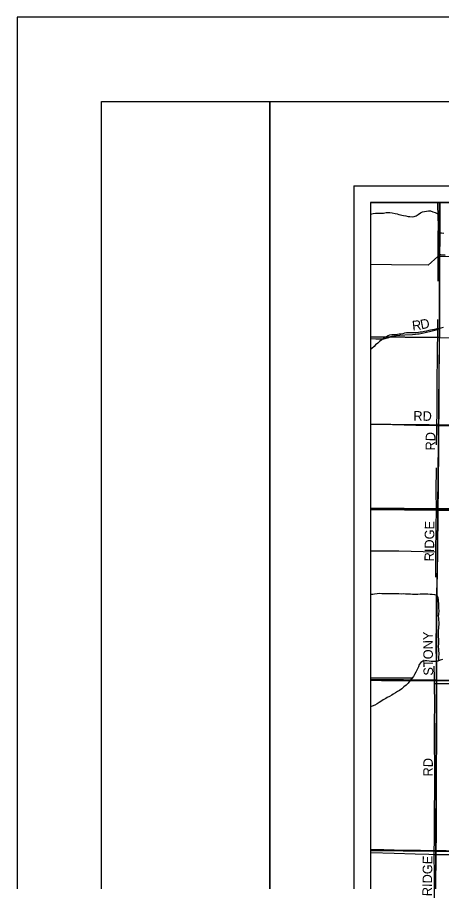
# Model space of a CAD drawing. Extents: x 0 to 34, y 0 to 22.
# Drawn here: x 0 to 2.52, y 16.87 to 22 of the extents above; entities that cross this region are included whole.
import ezdxf

# ---------------------------------------------------------------- set-up
doc = ezdxf.new("R2010")
doc.units = 0
for name, color, linetype in [('GM_X_City_Street', 7, 'Continuous'), ('GM_X_County_Road', 7, 'Continuous'), ('GM_X_County_Road_Text', 7, 'Continuous'), ('GM_X_Major_River', 7, 'Continuous'), ('GM_X_Minor_River', 7, 'Continuous'), ('GM_X_Section', 7, 'Continuous'), ('GM_X_State_Route', 7, 'Continuous'), ('GM_X_Township_Road', 7, 'Continuous'), ('GM_X_Township_Road_Text', 7, 'Continuous'), ('GM_X_US_Route', 7, 'Continuous'), ('SH_Border', 7, 'Continuous'), ('SH_Cut_Line', 7, 'Continuous'), ('SH_Data', 7, 'Continuous')]:
    doc.layers.add(name, color=color, linetype=linetype)

msp = doc.modelspace()

# ---------------------------------------------------------------- linework, layer by layer
at = {"layer": 'GM_X_City_Street'}
for points in [[(2.5083, 20.9), (2.1, 20.9), (2.1, 20.1033), (2.509, 20.0994)], [(3.5146, 20.9), (2.5083, 20.9), (2.509, 20.0994), (3.5083, 20.0811)], [(2.1, 20.1033), (2.1, 19.086), (2.4993, 19.0815), (2.509, 20.0994)], [(2.1, 19.086), (2.1, 18.0672), (2.4915, 18.0628), (2.4993, 19.0815)], [(2.1, 18.0672), (2.1, 17.0529), (2.4879, 17.0483), (2.4915, 18.0628)], [(2.1, 17.0529), (2.1, 16.0468), (2.4708, 16.042), (2.4803, 16.0422), (2.4865, 16.4094), (2.4879, 17.0483)]]:
    msp.add_lwpolyline(points, close=True, dxfattribs=at)
at = {"layer": 'GM_X_County_Road'}
for points in [[(2.5122, 20.5909), (2.5122, 20.5937), (2.5121, 20.6161), (2.5125, 20.6596), (2.5124, 20.7062), (2.5126, 20.7603), (2.5128, 20.7796), (2.513, 20.8363), (2.5134, 20.8803), (2.5135, 20.9)], [(2.5097, 20.1502), (2.5097, 20.1609), (2.5102, 20.1988), (2.5108, 20.3033), (2.511, 20.3791), (2.5113, 20.4463), (2.5121, 20.5234), (2.5121, 20.5533), (2.5121, 20.575), (2.5122, 20.5909)], [(2.5062, 19.5803), (2.5069, 19.6454), (2.507, 19.6853), (2.5071, 19.712), (2.5076, 19.7735), (2.5077, 19.8165), (2.5079, 19.8401), (2.5082, 19.8861), (2.5082, 19.906), (2.5087, 19.975), (2.509, 20.0304), (2.5092, 20.0763), (2.5094, 20.1111), (2.5096, 20.1435), (2.5097, 20.1502)], [(2.5016, 19.0733), (2.502, 19.114), (2.503, 19.1644), (2.5032, 19.2048), (2.5033, 19.226), (2.5038, 19.2944), (2.5047, 19.3677), (2.5052, 19.4119), (2.5053, 19.4492), (2.5062, 19.5338), (2.5062, 19.5742), (2.5062, 19.5803)], [(2.4932, 18.0623), (2.4936, 18.0677), (2.4937, 18.0694), (2.4938, 18.0714), (2.4938, 18.0995), (2.4938, 18.1225), (2.4935, 18.1399), (2.4925, 18.1667), (2.491, 18.2046), (2.4902, 18.2362), (2.4904, 18.3245), (2.4906, 18.36), (2.4908, 18.4128), (2.491, 18.4968), (2.4912, 18.5372), (2.4915, 18.5521), (2.4932, 18.5912), (2.495, 18.6378), (2.4972, 18.6844), (2.4979, 18.7024), (2.4982, 18.7279), (2.4987, 18.8025), (2.4992, 18.8585), (2.4995, 18.9058), (2.5004, 18.9909), (2.5013, 19.0456), (2.5016, 19.0699), (2.5016, 19.0723), (2.5016, 19.0733)]]:
    msp.add_lwpolyline(points, dxfattribs=at)
at = {"layer": 'GM_X_Major_River'}
msp.add_lwpolyline([(2.5271, 18.1874), (2.5133, 18.182), (2.4995, 18.1769), (2.4866, 18.1745), (2.4733, 18.174), (2.46, 18.1746), (2.4475, 18.1764), (2.4335, 18.1786), (2.4237, 18.1788), (2.4103, 18.1764), (2.3977, 18.1694), (2.3883, 18.1559), (2.3835, 18.1434), (2.3784, 18.131), (2.3681, 18.1107), (2.3614, 18.0971), (2.354, 18.0847), (2.3431, 18.0712), (2.333, 18.0589), (2.3229, 18.0469), (2.3113, 18.035), (2.2978, 18.0242), (2.2855, 18.0127), (2.2716, 18.003), (2.259, 17.9964), (2.2471, 17.9891), (2.234, 17.9806), (2.225, 17.9745), (2.2123, 17.9676), (2.1992, 17.9602), (2.1894, 17.9557), (2.1754, 17.9471), (2.1611, 17.9379), (2.1511, 17.9309), (2.1384, 17.9235), (2.1243, 17.9162), (2.1093, 17.9092), (2.1, 17.9052)], dxfattribs=at)
at = {"layer": 'GM_X_Minor_River'}
msp.add_line((2.3466, 18.0756), (2.1, 18.0766), dxfattribs=at)
for points in [[(2.4969, 20.9), (2.4971, 20.8695), (2.4985, 20.8391), (2.4999, 20.8329), (2.5008, 20.747), (2.5001, 20.7208), (2.4996, 20.6235), (2.4987, 20.5797), (2.5001, 20.4938), (2.5002, 20.4326)], [(2.1, 20.8316), (2.1146, 20.8352), (2.128, 20.8371), (2.1375, 20.8376), (2.1595, 20.837), (2.1762, 20.8377), (2.1926, 20.8399), (2.2044, 20.841), (2.2146, 20.8411), (2.2278, 20.8388), (2.2452, 20.8349), (2.2576, 20.8323), (2.2674, 20.8297), (2.2946, 20.8229), (2.3089, 20.8202), (2.3222, 20.8179), (2.332, 20.8168), (2.3464, 20.8153), (2.3582, 20.8165), (2.3704, 20.8203), (2.3828, 20.8287), (2.3972, 20.8389), (2.4076, 20.844), (2.4194, 20.847), (2.4316, 20.8493), (2.4438, 20.8509), (2.4563, 20.8498), (2.4691, 20.8456), (2.483, 20.8414), (2.4999, 20.8329)], [(2.5001, 20.7208), (2.5221, 20.7194), (2.5342, 20.7187)], [(3.1282, 20.5752), (3.0655, 20.5771), (2.9928, 20.5751), (2.9386, 20.5755), (2.8853, 20.5713), (2.8318, 20.5713), (2.7919, 20.571), (2.7441, 20.5719), (2.6865, 20.5751), (2.6114, 20.5765), (2.5431, 20.5796), (2.4987, 20.5797), (2.4415, 20.5289), (2.224, 20.5306), (2.1, 20.5313)], [(2.4975, 20.2053), (2.4967, 20.1486), (2.4955, 20), (2.4943, 19.8248), (2.4925, 19.6552), (2.4909, 19.5747), (2.4904, 19.4606)], [(2.5304, 20.1583), (2.5166, 20.1549), (2.5059, 20.1526), (2.4925, 20.1491), (2.4799, 20.1465), (2.4669, 20.1438), (2.4555, 20.1422), (2.4452, 20.1402), (2.4318, 20.1364), (2.4192, 20.1334), (2.4051, 20.1311), (2.3944, 20.1295), (2.3837, 20.1283), (2.37, 20.1272), (2.3602, 20.1267), (2.3469, 20.1263), (2.3343, 20.1267), (2.3222, 20.1263), (2.3127, 20.1254), (2.302, 20.1234), (2.2905, 20.1211), (2.2798, 20.1191), (2.2692, 20.1175), (2.2596, 20.1159), (2.2471, 20.1147), (2.2368, 20.1143), (2.2254, 20.1138), (2.2121, 20.1116), (2.2017, 20.1077), (2.1886, 20.1005), (2.1762, 20.0917), (2.1657, 20.0844), (2.1529, 20.0749), (2.1428, 20.0653), (2.1299, 20.0542), (2.1202, 20.0454), (2.1081, 20.0339), (2.1, 20.0265)], [(3.1233, 19.571), (2.8675, 19.5726), (2.6853, 19.5733), (2.4909, 19.5747), (2.3688, 19.5767), (2.1601, 19.5815), (2.1, 19.5823)], [(2.4887, 19.3238), (2.4882, 19.1847), (2.4886, 19.0805), (2.4869, 18.9668), (2.4863, 18.8247), (2.4851, 18.6753)], [(2.7507, 19.0855), (2.7454, 19.0819), (2.7403, 19.0816), (2.557, 19.0812), (2.4886, 19.0805), (2.3679, 19.0801), (2.2856, 19.0817), (2.2529, 19.0812)], [(2.4863, 18.8247), (2.2677, 18.829), (2.1, 18.8298)], [(2.5047, 18.1788), (2.5051, 18.1941), (2.5062, 18.2044), (2.5069, 18.2165), (2.5068, 18.2268), (2.5056, 18.2363), (2.5044, 18.2489), (2.504, 18.2607), (2.5046, 18.2812), (2.5054, 18.2964), (2.505, 18.3089), (2.5037, 18.3185), (2.5025, 18.3284), (2.5024, 18.3379), (2.5027, 18.3493), (2.5034, 18.3599), (2.5044, 18.3698), (2.5048, 18.3812), (2.5063, 18.3948), (2.5063, 18.4074), (2.5051, 18.4203), (2.5047, 18.4318), (2.5043, 18.4439), (2.5057, 18.4545), (2.5064, 18.477), (2.506, 18.4899), (2.5055, 18.4998), (2.5046, 18.5093), (2.5046, 18.5211), (2.5041, 18.5314), (2.5033, 18.5413), (2.5006, 18.5543), (2.4945, 18.567), (2.4821, 18.5708), (2.4662, 18.5728), (2.4544, 18.5727), (2.4408, 18.5743), (2.4268, 18.575), (2.4169, 18.5746), (2.407, 18.5737), (2.3937, 18.5737), (2.3796, 18.5718), (2.3633, 18.5715), (2.3496, 18.5723), (2.3379, 18.5742), (2.3209, 18.575), (2.3072, 18.5751), (2.2939, 18.5758), (2.2833, 18.5754), (2.2678, 18.5762), (2.2571, 18.5765), (2.2446, 18.5761), (2.2298, 18.5758), (2.2192, 18.5757), (2.2089, 18.5756), (2.196, 18.5756), (2.1835, 18.5756), (2.1672, 18.5772), (2.1535, 18.5776), (2.1391, 18.5768), (2.1238, 18.5746), (2.1132, 18.5734), (2.1018, 18.5722), (2.1, 18.5728)], [(2.476, 18.1459), (2.4771, 18.0771), (2.4781, 18.0432), (2.4793, 17.9146), (2.4784, 17.8158), (2.4785, 17.6976), (2.4786, 17.5432), (2.4789, 17.4216), (2.4779, 17.2775), (2.4774, 17.1296), (2.4761, 17.0289), (2.4773, 16.9103), (2.4771, 16.7989), (2.4777, 16.6578), (2.479, 16.5464), (2.4756, 16.3998), (2.474, 16.2629), (2.4723, 16.1379), (2.4714, 16.025)], [(2.4788, 18.0443), (2.6292, 18.0442), (2.7981, 18.0431), (2.9662, 18.0429), (2.9984, 18.0416), (3.1078, 18.0415)], [(2.1, 17.04), (2.1033, 17.04), (2.2406, 17.0361), (2.3642, 17.0318), (2.4454, 17.0298), (2.4761, 17.0289), (2.5638, 17.0291), (2.6591, 17.029), (2.7445, 17.0292), (2.8488, 17.0277), (2.8978, 17.0267)]]:
    msp.add_lwpolyline(points, dxfattribs=at)
at = {"layer": 'GM_X_Section'}
for points in [[(2.509, 20.0994), (3.5083, 20.0811), (3.5044, 19.0749), (2.4993, 19.0815)], [(3.5044, 19.0749), (3.5019, 18.057), (2.4915, 18.0628), (2.4993, 19.0815)], [(3.5019, 18.057), (3.4934, 17.0475), (2.4879, 17.0483), (2.4915, 18.0628)]]:
    msp.add_lwpolyline(points, close=True, dxfattribs=at)
msp.add_lwpolyline([(3.4773, 16.1435), (3.4754, 16.0365), (3.4686, 16.0366), (2.4803, 16.0422), (2.4865, 16.4094), (2.4879, 17.0483), (3.4934, 17.0475), (3.4907, 16.8935)], dxfattribs=at)
at = {"layer": 'GM_X_State_Route'}
msp.add_lwpolyline([(2.1, 18.0629), (2.1654, 18.0625), (2.198, 18.0623), (2.2695, 18.0621), (2.313, 18.0623), (2.372, 18.0625), (2.4559, 18.0623), (2.4932, 18.0623), (2.5212, 18.0621), (2.6253, 18.0616), (2.6921, 18.0614), (2.8211, 18.0604), (2.9283, 18.0596), (3.0076, 18.059), (3.0558, 18.0585), (3.1024, 18.0582), (3.1723, 18.0579), (3.2531, 18.0572), (3.2826, 18.057), (3.3479, 18.0565), (3.4318, 18.0561), (3.4753, 18.0558), (3.4975, 18.0561)], dxfattribs=at)
at = {"layer": 'GM_X_Township_Road'}
for points in [[(2.5122, 20.5909), (2.5165, 20.5907), (2.5426, 20.5899)], [(2.1, 20.0918), (2.1303, 20.0913), (2.167, 20.0906), (2.1744, 20.0909), (2.1793, 20.0913), (2.1823, 20.0917), (2.1861, 20.0926), (2.1927, 20.0945), (2.2074, 20.0995), (2.2198, 20.1036), (2.2241, 20.1049), (2.2288, 20.1061), (2.2342, 20.1072), (2.241, 20.1084), (2.2527, 20.1098), (2.2744, 20.1117), (2.3023, 20.1139), (2.3482, 20.1172), (2.3661, 20.1185), (2.3785, 20.1197), (2.3884, 20.1211), (2.4055, 20.1239), (2.4238, 20.1276), (2.4584, 20.1354), (2.4819, 20.1414), (2.4968, 20.1457), (2.5021, 20.1476), (2.5097, 20.1502)], [(2.1, 19.5851), (2.2194, 19.5836), (2.3307, 19.5822), (2.3917, 19.5816), (2.4476, 19.581), (2.5062, 19.5803)], [(2.5062, 19.5803), (2.5415, 19.5799), (2.5664, 19.5798), (2.5956, 19.5796), (2.636, 19.5795), (2.7946, 19.5788), (2.8996, 19.5781), (3.0315, 19.5773), (3.1795, 19.5762), (3.3069, 19.5754), (3.5035, 19.5744)], [(2.4899, 17.0522), (2.49, 17.0585), (2.4903, 17.0815), (2.4906, 17.1088), (2.491, 17.1461), (2.4912, 17.1996), (2.4912, 17.2649), (2.4914, 17.3072), (2.4913, 17.3402), (2.4916, 17.3806), (2.4917, 17.4148), (2.4919, 17.4453), (2.4919, 17.4851), (2.4918, 17.5448), (2.492, 17.5964), (2.4925, 17.6449), (2.4929, 17.694), (2.493, 17.7624), (2.4929, 17.837), (2.4927, 17.8812), (2.4927, 17.9446), (2.4929, 17.9875), (2.493, 18.0298), (2.4929, 18.0537), (2.4929, 18.0553), (2.4929, 18.0568), (2.4932, 18.0623)], [(2.1, 17.0588), (2.1409, 17.0579), (2.1782, 17.0574), (2.2404, 17.0561), (2.3056, 17.055), (2.3585, 17.0541), (2.3958, 17.0535), (2.4237, 17.053), (2.4672, 17.0525), (2.4899, 17.0522)], [(2.4824, 16.0401), (2.4822, 16.0478), (2.4819, 16.0571), (2.482, 16.0944), (2.4824, 16.1504), (2.4829, 16.2095), (2.4833, 16.2561), (2.484, 16.3245), (2.4846, 16.3959), (2.4847, 16.427), (2.4858, 16.5016), (2.4863, 16.5327), (2.4865, 16.5576), (2.4865, 16.6166), (2.4866, 16.6539), (2.4861, 16.7068), (2.4858, 16.7379), (2.4865, 16.8032), (2.4874, 16.8529), (2.4881, 16.9026), (2.4887, 16.9617), (2.4891, 17.0021), (2.4899, 17.0522)], [(2.4899, 17.0522), (2.5014, 17.0521), (2.548, 17.0515), (2.604, 17.0508), (2.6723, 17.0498), (2.7438, 17.0491), (2.7966, 17.0484), (2.8526, 17.0478), (2.8681, 17.0476), (2.921, 17.047), (2.952, 17.0465), (2.9614, 17.0463), (2.9987, 17.0459), (3.0919, 17.0449), (3.1447, 17.0443), (3.1851, 17.0439), (3.2411, 17.0432), (3.3343, 17.0421), (3.3623, 17.0417), (3.3965, 17.0412), (3.4617, 17.0405), (3.4866, 17.0403), (3.4885, 17.0403)]]:
    msp.add_lwpolyline(points, dxfattribs=at)
at = {"layer": 'GM_X_US_Route'}
for points in [[(7.5667, 20.9), (2.1, 20.9), (2.1, 19.0771), (2.5014, 19.0729), (3.5046, 19.0712)], [(3.5046, 19.0712), (2.5014, 19.0729), (2.1, 19.0771), (2.1, 14.1)]]:
    msp.add_lwpolyline(points, dxfattribs=at)
at = {"layer": 'SH_Border'}
for points in [[(0.5, 21.5), (1.5, 21.5), (1.5, 0.5), (0.5, 0.5)], [(1.5, 21.5), (33.5, 21.5), (33.5, 0.5), (1.5, 0.5)]]:
    msp.add_lwpolyline(points, close=True, dxfattribs=at)
at = {"layer": 'SH_Cut_Line'}
msp.add_lwpolyline([(0, 0), (34, 0), (34, 22), (0, 22)], close=True, dxfattribs=at)
msp.add_lwpolyline([(7.5667, 20.9), (2.1, 20.9), (2.1, 14.1)], dxfattribs=at)
at = {"layer": 'SH_Data'}
for p, q in [((2, 21), (9, 21)), ((2, 21), (2, 14)), ((2.1, 20.9), (2.1, 14.1)), ((2.1, 20.9), (8.9, 20.9))]:
    msp.add_line(p, q, dxfattribs=at)

# ---------------------------------------------------------------- texts
at = {"layer": 'GM_X_County_Road_Text'}
for s, rotation, p in [('RD', 89.5126, (2.4833, 19.4275)), ('RIDGE', 89.3516, (2.4766, 18.7685)), ('STONY', 90.8095, (2.4716, 18.0911))]:
    msp.add_text(s, height=0.05682, rotation=rotation, dxfattribs=at).set_placement(p)
at = {"layer": 'GM_X_Township_Road_Text'}
for s, height, rotation, p in [('R', 0.0568, 6.638, (2.3496, 20.14)), ('D', 0.0568, 11.8405, (2.4015, 20.1463)), ('RD', 0.05682, 359.0164, (2.3535, 19.605)), ('RD', 0.05682, 89.5104, (2.4691, 17.4917)), ('RIDGE', 0.05682, 89.3255, (2.4641, 16.7804))]:
    msp.add_text(s, height=height, rotation=rotation, dxfattribs=at).set_placement(p)

doc.saveas('drawing.dxf')
